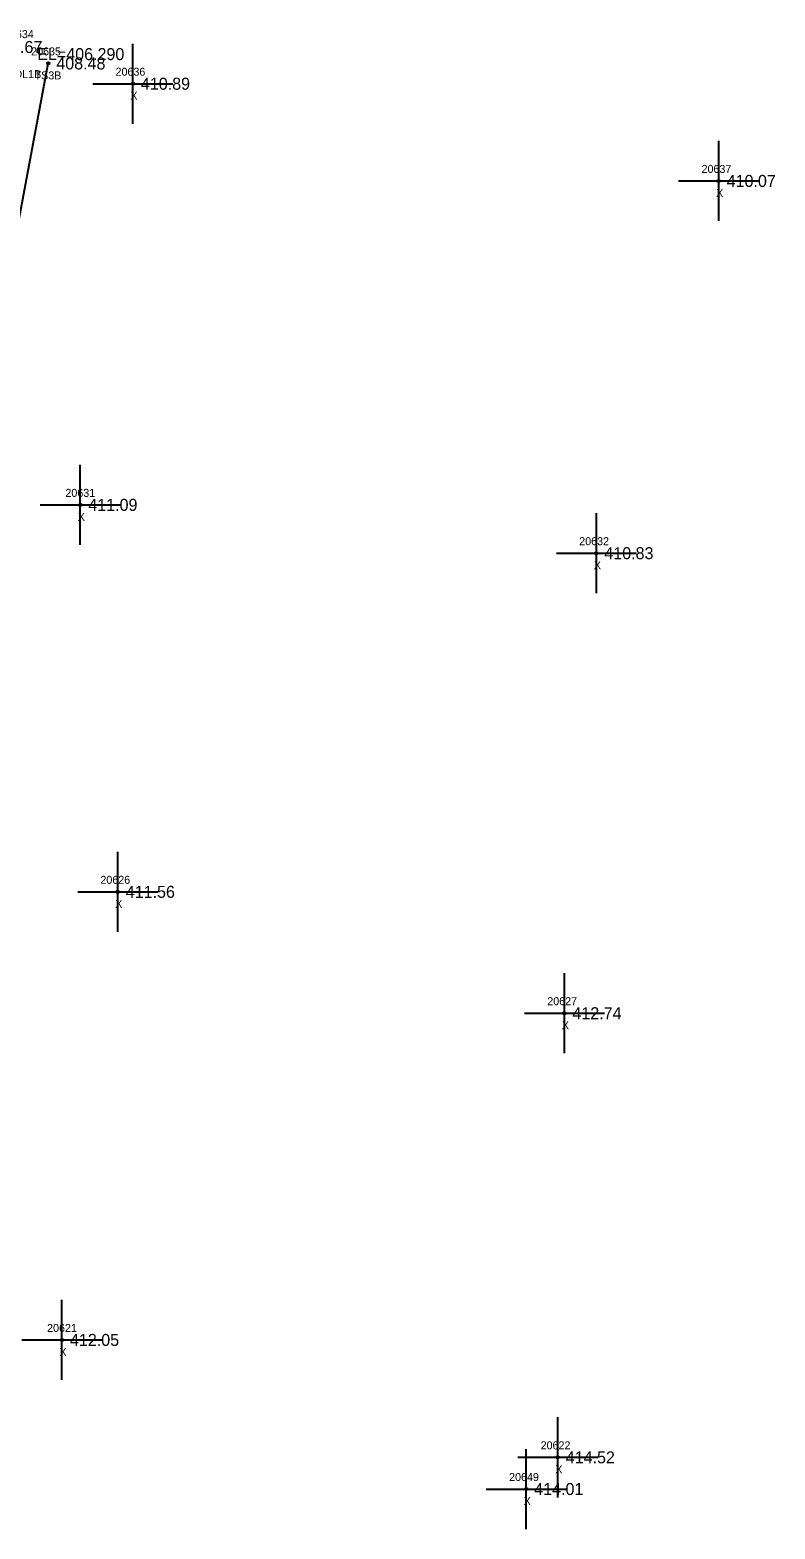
# Model space of a CAD drawing. Extents: x 2116373 to 2118139, y 979529 to 981026.
# Drawn here: x 2118046.4 to 2118139.5, y 980826 to 981013.4 of the extents above; entities that cross this region are included whole.
import ezdxf

# ---------------------------------------------------------------- set-up
doc = ezdxf.new("R2010")
doc.units = 0
for name, color, linetype in [('RD_DTM_BkLn2', 7, 'Continuous'), ('RD_DTM_BkLn_txCode', 7, 'Continuous'), ('RD_EX_H2O_txCode', 7, 'Continuous'), ('RD_EX_Misc', 7, 'Continuous'), ('RD_EX_Misc_txCode', 7, 'Continuous'), ('RD_EX_TX_H2O_ELEV', 7, 'Continuous'), ('RD_EX_TX_Misc_ELEV', 7, 'Continuous'), ('RD_SMD_Locator', 7, 'Continuous')]:
    doc.layers.add(name, color=color, linetype=linetype)

msp = doc.modelspace()

# ---------------------------------------------------------------- linework, layer by layer
at = {"layer": 'RD_DTM_BkLn2'}
msp.add_lwpolyline([(2118025.45, 980857.32), (2118028.74, 980908.94), (2118039.02, 980957.63), (2118048.69, 981009.19)], dxfattribs=at)
at = {"layer": 'RD_EX_Misc'}
for p, q in [((2118059.26, 981001.65), (2118059.26, 981011.65)), ((2118054.26, 981006.65), (2118064.26, 981006.65)), ((2118132.43, 980989.5), (2118132.43, 980999.5)), ((2118127.43, 980994.5), (2118137.43, 980994.5)), ((2118052.69, 980949.02), (2118052.69, 980959.02)), ((2118047.69, 980954.02), (2118057.69, 980954.02)), ((2118117.15, 980942.98), (2118117.15, 980952.98)), ((2118112.15, 980947.98), (2118122.15, 980947.98)), ((2118057.37, 980900.66), (2118057.37, 980910.66)), ((2118052.37, 980905.66), (2118062.37, 980905.66)), ((2118113.16, 980885.49), (2118113.16, 980895.49)), ((2118108.16, 980890.49), (2118118.16, 980890.49)), ((2118050.4, 980844.66), (2118050.4, 980854.66)), ((2118045.4, 980849.66), (2118055.4, 980849.66)), ((2118112.33, 980829.99), (2118112.33, 980839.99)), ((2118108.39, 980826.03), (2118108.39, 980836.03)), ((2118107.33, 980834.99), (2118117.33, 980834.99)), ((2118103.39, 980831.03), (2118113.39, 980831.03))]:
    msp.add_line(p, q, dxfattribs=at)
at = {"layer": 'RD_SMD_Locator'}
for centre in [(2118048.69, 981009.19), (2118059.26, 981006.65), (2118132.43, 980994.5), (2118052.69, 980954.02), (2118117.15, 980947.98), (2118057.37, 980905.66), (2118113.16, 980890.49), (2118050.4, 980849.66), (2118112.33, 980834.99), (2118108.39, 980831.03)]:
    msp.add_circle(centre, 0.15, dxfattribs=at)

# ---------------------------------------------------------------- texts
at = {"layer": 'RD_DTM_BkLn_txCode'}
for s, p in [('20635', (2118046.55, 981010.19)), ('TS3B', (2118046.98, 981007.19))]:
    msp.add_text(s, height=1, dxfattribs=at).set_placement(p)
at = {"layer": 'RD_EX_H2O_txCode'}
for s, p in [('20634', (2118043.16, 981012.35)), ('ODL1B', (2118043.42, 981007.35))]:
    msp.add_text(s, height=1, dxfattribs=at).set_placement(p)
at = {"layer": 'RD_EX_Misc_txCode'}
for s, p in [('20636', (2118057.09, 981007.65)), ('X', (2118058.94, 981004.65)), ('20637', (2118130.29, 980995.5)), ('X', (2118132.11, 980992.5)), ('20631', (2118050.83, 980955.02)), ('X', (2118052.37, 980952.02)), ('20632', (2118115.01, 980948.98)), ('X', (2118116.84, 980945.98)), ('20626', (2118055.2, 980906.66)), ('X', (2118057.05, 980903.66)), ('20627', (2118111.02, 980891.49)), ('X', (2118112.84, 980888.49)), ('20621', (2118048.54, 980850.66)), ('X', (2118050.08, 980847.66)), ('20622', (2118110.19, 980835.99)), ('X', (2118112.02, 980832.99)), ('20649', (2118106.25, 980832.03)), ('X', (2118108.07, 980829.03))]:
    msp.add_text(s, height=1, dxfattribs=at).set_placement(p)
at = {"layer": 'RD_EX_TX_H2O_ELEV'}
msp.add_text('EL=406.290', height=1.5, dxfattribs=at).set_placement((2118047.31, 981009.6))
at = {"layer": 'RD_EX_TX_Misc_ELEV'}
for s, p in [('407.67', (2118041.81, 981010.49)), ('408.48', (2118049.69, 981008.44)), ('410.89', (2118060.26, 981005.9)), ('410.07', (2118133.43, 980993.75)), ('411.09', (2118053.69, 980953.27)), ('410.83', (2118118.15, 980947.23)), ('411.56', (2118058.37, 980904.91)), ('412.74', (2118114.16, 980889.74)), ('412.05', (2118051.4, 980848.91)), ('414.52', (2118113.33, 980834.24)), ('414.01', (2118109.39, 980830.28))]:
    msp.add_text(s, height=1.5, dxfattribs=at).set_placement(p)

doc.saveas('drawing.dxf')
